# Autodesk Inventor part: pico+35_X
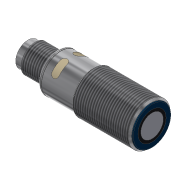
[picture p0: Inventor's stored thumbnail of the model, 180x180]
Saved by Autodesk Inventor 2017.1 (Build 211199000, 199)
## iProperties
Shininess: 20.0
Length Units: 11269
Angle Units: 11279
Time Units: 11290
Mass Units: 11283
Length Display Precision: 2
Angle Display Precision: 2
Part Number: pico+35_X
Material: Nichtrostender Stahl - 440C
Document SubType Name: Modellieren
Description: Ipc-25 /CXX/M18
Checked By: Alves
Created: 2005-08
Designer: Ohle
Manufacturer: Standard
Standards Organization: Custom
Appearance: Aluminium - poliert
Density: 0.0
Volumn: 0.0
Area: 0.0
PropertySet Name: Model Information
Control State: 0
Master: False
Checked Out: False
BESTELLNUMMER: Ipc-25 /CXX/M18
ME: ST
Title: Ipc Sensoren
Author: Ohle
Comments: keine Bemerkung
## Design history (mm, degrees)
sketch "Skizze10"
  geometry: L1 (-43, 0)-(1.5, 0); L2 (-39, 6.5)-(-39, 7.25); L3 (-45.9, 8)-(-45.9, 8); L4 (-23.25, 9)-(0.25, 9); L5 (1.5, 7.95)-(1.5, 6); L6 (1.49, 6)-(1.49, 4.8); L7 (1.5, 4.8)-(1.5, 0); L8 (1.5, 0)-(-81.71, 0); L9 (1.142, 8.25)-(1.142, 8.25); L10 (-24, 8.25)-(-23.25, 9); L11 (1, 8.25)-(0.25, 9); L12 (-50.5, 6)-(-39.5, 6); L13 (-37.4, 8.25)-(-24, 8.25); L14 (-51, 4.5)-(-43, 4.5); L15 (-43, 0)-(-43, 4.5); L16 (-37.5, 8.25)-(-38, 8.25); L17 (1, 8.25)-(1, 8.25); L18 (-39.5, 6)-(-39, 6.5); L19 (-51, 5.5)-(-51, 4.5); L20 (-51, 5.5)-(-50.5, 6); L21 (-37.5, 8.25)-(-37.5, 8.15); L22 (-37.5, 8.15)-(-37.4, 8.15); L23 (-37.4, 8.15)-(-37.4, 8.25); L24 (1.49, 4.8)-(1.5, 4.8); L25 (1, 8.25)-(1.2, 8.25); L26 (1.49, 6)-(1.5, 6); A1 r 1 centre (-38, 7.25) between (-38, 8.25) and (-39, 7.25); A2 r 0.3 centre (1.2, 7.95) between (1.5, 7.95) and (1.2, 8.25); 3 further points
  constraints: 52 end point, 7 parallel, 6 point on line, 4 perpendicular, 4 point on circle, 4 tangent, 2 centre point, 1 collinear, 1 horizontal
  dimensions: "d138" = 9 distance between parallel lines of L4 L8; "d164" = 1.5 distance from line of point (0, 0) L5; "d171" = 4.5 distance between parallel lines of L14 L1; "d250" = 0.75 distance from line of L11.start L4; "d252" = 6 distance from line of L8 L5.end; "d256" = 45 deg angle of L4 L10; "d257" = 8.25 distance between parallel lines of L8 L13; "d263" = 8.25 distance between parallel lines of L8 L16; "d266" = 12 distance from line of L2 L19.start; "d269" = 6 distance between parallel lines of L8 L12; "d289" = 135 deg angle of L11 L4; "d290" = 0.5 horizontal distance of L12.end L2.start; "d291" = 45 deg angle of L18 L12 (derived); "d293" = 0.5 horizontal distance of L19.start L12.start; "d294" = 45 deg angle of L20 L12 (derived); "d295" = 8 distance of L14.start L14.end; "d296" = 1.5 distance of L16.start point (-39, 8.25); "d297" = 0.1 distance of L21.end L22.end; "d298" = 8.15 distance between parallel lines of L22 L1; "d299" = 15 distance from line of L10.start L2; "d300" = 1 radius of A1; "d331" = 4.8 distance between parallel lines of L1 L24; "d333" = 0.01 distance between parallel lines of L7 L6; "d334" = 0.3 radius of A2; "d335" = 0.5 distance from line of L5 L11.start; "d336" = 0.01 distance between parallel lines of L6 L5; "d337" = 25 distance of L10.start L11.start
revolve "Grundkörper pico+" sketch "Skizze10" stored, may be unused: angle "d168" = 90 deg
feature "Gewinde M12" dims "d174" = 10, "d175" = 0
feature "Gewinde M 18" dims "d179" = 10, "d180" = 0
workplane "Arbeitsebene1"
workplane "Arbeitsebene2"
sketch "Skizze13"
  geometry: L1 (-3.409, -3.409)-(3.61, 3.61); L2 (-3.439, 3.439)-(4.105, -4.105); L3 (-12.6, 0)-(12.6, 0) reference; C1 r 0.5 at (2.121, -2.121); C2 r 0.5 at (2.121, 2.121); C3 r 0.5 at (-2.121, 2.121); C4 r 0.5 at (-2.121, -2.121); C5 r 4.5 at (0, 0) reference; C6 r 0.5 at (0, 0); A1 r 3 centre (0, 0) between (-2.121, 2.121) and (2.121, 2.121); 2 further points
  constraints: 6 centre point, 6 point on line, 4 coincident, 4 end point, 4 equal radius, 4 point on circle, 1 horizontal alignment, 1 perpendicular
  dimensions: "d208" = 1 diameter of C3; "d209" = 6 diameter of A1
extrude "Pole" join sketch "Skizze13" distance "d212" = 7; taper "d213" = 0 deg
fillet "Rundung Pole" dims "d214" = 0.5
sketch "Skizze14"
  geometry: C1 r 0.5 at (0, -4.5); A1 r 4.5 centre (0, 0) between (4.435, -0.762) and (4.435, 0.762); A2 r 4.5 centre (0, 0) between (0, 4.5) and (0.499, 4.472) reference; A3 r 0.5 centre (0, 4.5) between (-0.499, 4.472) and (0.499, 4.472); 3 further points
  constraints: 9 point on circle, 3 centre point, 3 coincident, 1 horizontal alignment, 1 vertical alignment
  dimensions: "d215" = 9 diameter of A1; "d280" = 1 diameter of A3; "d330" = 1 diameter of C1
extrude "Verdrehsicherung" join sketch "Skizze14" distance "d217" = 7; taper "d218" = 0 deg
sketch "Skizze18"
  geometry: C1 r 7.25 at (0, 0) reference; C2 r 1 at (-8.15, 0)
  constraints: 1 centre point, 1 horizontal alignment
  dimensions: "d328" = 2 diameter of C2; "d329" = 8.15 distance of C1.centre C2.centre
extrude "Bohrung Ausrichtung" cut sketch "Skizze18" distance "d316" = 0.75; taper "d317" = 0 deg
workplane "Arbeitsebene4"
sketch "Skizze19"
  geometry: L1 (-39, 0)-(-30.18, 0); L2 (-34.7, -7.5)-(-34.7, -3); L3 (-31.7, -7.5)-(-31.7, -3); L4 (-31.7, 3)-(-31.7, 7.5); L5 (-34.7, 3)-(-34.7, 7.5); A1 r 1.5 centre (-33.2, 3) between (-31.7, 3) and (-34.7, 3); A2 r 1.5 centre (-33.2, -3) between (-34.7, -3) and (-31.7, -3); A3 r 1.5 centre (-33.2, 7.5) between (-31.7, 7.5) and (-34.7, 7.5); A4 r 1.5 centre (-33.2, -7.5) between (-34.7, -7.5) and (-31.7, -7.5); 4 further points; 1 other entity
  constraints: 10 end point, 8 point on circle, 8 tangent, 4 centre point, 3 equal radius, 2 vertical alignment, 1 horizontal, 2 other
  dimensions: "d319" = 3 diameter of A2; "d320" = 6 distance of A2.centre A1.centre; "d321" = 4.5 distance of A1.centre A3.centre; "d322" = 4.5 distance of A4.centre A2.centre; "d323" = 3 distance from line of A2.centre L1; "d324" = 5.8 dimension on A1.centre; "d325" = 5.8 dimension on A2.centre
feature "Prägen LED-Fenster" sketch "Skizze19" dims "d326" = 0.01, "d327" = 0
sketch "Skizze20"
  geometry: C1 r 5.5 at (0, 0); C2 r 4.5 at (0, 0); C3 r 4.15 at (0, 0); C4 r 5.25 at (0, 0); 2 further points
  constraints: 4 centre point
  dimensions: "d338" = 8.3 diameter of C3; "d339" = 10.5 diameter of C4
extrude "Extrusion5" join sketch "Skizze20" stored distance "d340" = 1; taper "d341" = 0 deg
sketch "Skizze21"
  geometry: C1 r 5.25 at (0, 0) reference; C2 r 10.117 at (0, 0); 1 further point
  constraints: 1 centre point
extrude "Extrusion6" cut sketch "Skizze21" distance "d342" = 2.6; taper "d343" = 0 deg
chamfer "Fase2" distance "d344" = 0.75; stored, may be unused: second distance "d345" = 2, angle "d346" = 30 deg
node "Volumenkörper1"
node "Volumenkörper"
node "Flächenkörper"
other parameters: "d10" = 14, "d73" = -35, "d130" = 0.2, "d207" = -95.5, "d318" = 8.25
